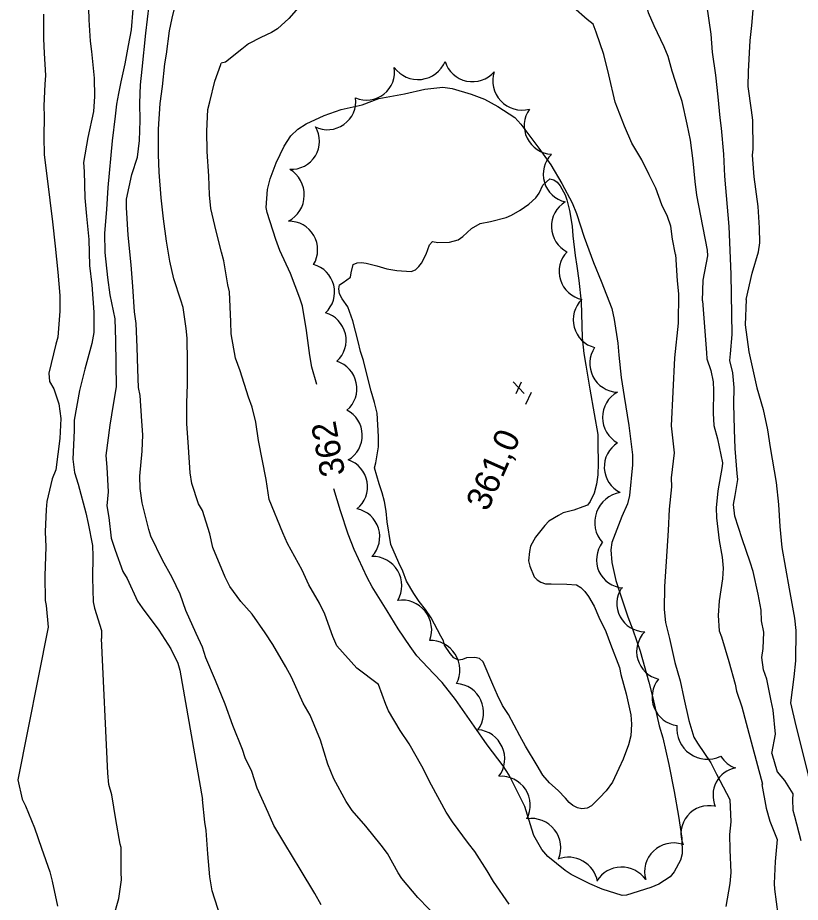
# Model space of a CAD drawing. Extents: x 287698 to 290158, y 5234163 to 5237182.
# Drawn here: x 288457.5 to 288552.3, y 5235917.4 to 5236024.6 of the extents above; entities that cross this region are included whole.
import ezdxf

# ---------------------------------------------------------------- set-up
doc = ezdxf.new("R2010")
doc.units = 0
for name, color, linetype in [('Niveau 1', 7, 'Continuous'), ('Niveau 2', 7, 'Continuous'), ('Niveau 3', 7, 'Continuous'), ('Niveau 4', 7, 'Continuous'), ('Niveau 44', 7, 'Continuous')]:
    doc.layers.add(name, color=color, linetype=linetype)

msp = doc.modelspace()

# ---------------------------------------------------------------- linework, layer by layer
at = {"layer": 'Niveau 1'}
for points in [[(288545.79, 5235990.47), (288546.52, 5235993.67), (288547.28, 5235996.23), (288547.44, 5235997.35), (288547.4, 5235999.16), (288547.23, 5236001.73), (288546.75, 5236005.33), (288546.55, 5236007.98), (288546.63, 5236008.7), (288546.57, 5236012.21), (288546.43, 5236013.41), (288546.01, 5236016.31), (288546.07, 5236018.11), (288546.25, 5236021.86), (288546.45, 5236023.69), (288546.8, 5236027.53)], [(288471.43, 5236025.67), (288471.22, 5236023.17), (288470.86, 5236021.27), (288470.44, 5236019.03), (288469.96, 5236016.86), (288469.66, 5236015.47), (288469.42, 5236014.16), (288469.25, 5236012.71), (288468.92, 5236009.7), (288468.37, 5236004.07), (288468.22, 5236001.39), (288467.96, 5235998.5), (288468, 5235996.15), (288468.32, 5235993.13), (288468.62, 5235991.04), (288469.21, 5235988.11), (288469.32, 5235985.49), (288469.37, 5235979.88), (288469.02, 5235977.75), (288468.64, 5235975.24), (288468.14, 5235971.54), (288468.25, 5235970.15), (288468.4, 5235967.14), (288468.25, 5235965.44), (288468.51, 5235964.03), (288468.79, 5235961.51), (288469.25, 5235960.07), (288470.21, 5235957.5), (288470.72, 5235956.62), (288471.98, 5235953.89), (288472.53, 5235953.06), (288474.57, 5235950.37), (288476.02, 5235948.12), (288476.88, 5235946.38), (288477.1, 5235945.5), (288479.85, 5235929.82)], [(288545.79, 5235990.47), (288545.64, 5235987.4), (288546.09, 5235984.12), (288547.05, 5235979.75), (288547.85, 5235977.13), (288548.35, 5235974.65), (288548.67, 5235972.5), (288549.42, 5235968.27), (288549.68, 5235965.62), (288549.87, 5235962.95), (288550.11, 5235960.4), (288550.53, 5235957.87), (288551, 5235955.39), (288551.64, 5235951.81), (288551.79, 5235950.32), (288551.76, 5235946.63), (288551.57, 5235944.7), (288551.17, 5235941.54), (288551.8, 5235938.75), (288553.24, 5235932.97), (288555.16, 5235921.59)], [(288482.41, 5235914.47), (288481.02, 5235918.77), (288480.73, 5235920.47), (288480.52, 5235923.25), (288480.3, 5235926.08), (288480.13, 5235927.09), (288479.85, 5235929.82)]]:
    msp.add_lwpolyline(points, dxfattribs=at)
at = {"layer": 'Niveau 2'}
for points in [[(288508.64, 5235915.2), (288505.96, 5235917.96), (288504.01, 5235920.24), (288503.6, 5235920.95), (288502.3, 5235923.26), (288501.53, 5235924.29), (288499.67, 5235926.61), (288498.01, 5235928.51), (288497.27, 5235929.59), (288495.77, 5235932.34), (288495.07, 5235934.1), (288494.15, 5235937.01), (288492.9, 5235940.06), (288492.06, 5235941.52), (288490.65, 5235944.66), (288489.96, 5235945.93), (288488.4, 5235948.62), (288487.47, 5235950.06), (288485.87, 5235952.32), (288484.51, 5235953.83), (288483.17, 5235955.66), (288482.61, 5235956.79), (288481.11, 5235960.41), (288480.75, 5235962.03), (288479.84, 5235964.87), (288479.37, 5235965.7), (288478.57, 5235968.14), (288478.35, 5235969.45), (288478.14, 5235972.54), (288477.97, 5235975.43), (288477.94, 5235977.94), (288478.04, 5235980.14), (288478.02, 5235982.9), (288478.01, 5235985.79), (288477.86, 5235986.97), (288477.53, 5235989.48), (288477.22, 5235990.37), (288476.39, 5235992.96), (288475.89, 5235995.11), (288475.5, 5235997.55), (288475.12, 5236000.26), (288474.84, 5236002.78), (288474.59, 5236005.92), (288474.51, 5236008.07), (288474.54, 5236011.14), (288474.74, 5236014.22), (288475.02, 5236016.29), (288475.27, 5236019.03), (288475.48, 5236020.24), (288475.87, 5236023.07), (288476.18, 5236024.59), (288476.91, 5236027.56)], [(288540.5, 5235990.31), (288540.56, 5235992.8), (288541.11, 5235995.75), (288541.09, 5235996.47), (288540.29, 5236000.62), (288539.78, 5236003.14), (288539.59, 5236004.77), (288539.36, 5236007.27), (288539.01, 5236009.81), (288538.63, 5236011.75), (288538, 5236014.48), (288537.56, 5236015.76), (288536.79, 5236018.16), (288536.33, 5236019.93), (288535.85, 5236021.1), (288534.61, 5236023.66), (288533.95, 5236025.25), (288533.62, 5236026.63), (288533.22, 5236028.42)], [(288466, 5236027.22), (288466.06, 5236024.38), (288466.23, 5236021.81), (288466.41, 5236020.54), (288466.72, 5236017.31), (288466.78, 5236015.08), (288466.64, 5236013.27), (288465.95, 5236010.1), (288465.42, 5236007.08), (288465.49, 5236005.99), (288465.6, 5236002.81), (288465.8, 5236000.58), (288466.06, 5235997.76), (288466.15, 5235994.61), (288466.43, 5235992.25), (288466.69, 5235988.95), (288466.69, 5235986.45), (288466.44, 5235985.14), (288465.58, 5235982), (288464.93, 5235979.42), (288464.3, 5235975.84), (288464.3, 5235974.59), (288464.15, 5235971.09), (288464.33, 5235969.49), (288464.77, 5235968.06), (288465.73, 5235964.61), (288466, 5235963.32), (288466.5, 5235960.62), (288466.56, 5235959.35), (288466.5, 5235956.72), (288466.59, 5235953.82), (288466.75, 5235953.02), (288467.61, 5235950.33), (288467.63, 5235949.36)], [(288492.12, 5236026.56), (288490.33, 5236024.55), (288488.97, 5236023.31), (288488.24, 5236022.85), (288486.94, 5236022.25), (288485.44, 5236021.49), (288484.62, 5236020.82), (288482.64, 5236019.26), (288482.14, 5236019.13), (288482.14, 5236019.13)], [(288494.23, 5235917.07), (288493.47, 5235918.43), (288491.7, 5235921.39), (288489.85, 5235924.46), (288488.51, 5235926.67), (288487.81, 5235928.24), (288486.49, 5235931.21), (288485.82, 5235933.22), (288485.02, 5235934.89), (288484.7, 5235935.91), (288483.55, 5235938.82), (288482.62, 5235941.38), (288481.42, 5235944.27), (288480.25, 5235947.03), (288479.84, 5235948.31), (288479.08, 5235949.97), (288477.82, 5235952.75), (288477.13, 5235954.74), (288476.16, 5235956.76), (288474.99, 5235958.84), (288473.6, 5235961.78), (288473.36, 5235962.59), (288472.56, 5235965.82), (288472.28, 5235967.54), (288472.24, 5235969.03), (288472.56, 5235972.08), (288472.62, 5235974.07), (288472.51, 5235975.71), (288472.28, 5235978.84), (288472.11, 5235979.81), (288472.02, 5235982.03), (288471.92, 5235984.7), (288471.8, 5235987.57), (288471.61, 5235988.99), (288471.41, 5235992.05), (288471.2, 5235994.67), (288470.86, 5235998.29), (288470.63, 5236001.63), (288470.66, 5236002.64), (288471.29, 5236005.61), (288471.98, 5236007.73), (288472.2, 5236009.76), (288472.28, 5236012.18), (288472.24, 5236014.28), (288472.33, 5236016.51), (288472.55, 5236018.42), (288473, 5236022.75), (288473.39, 5236026.17)], [(288527.6, 5236022.9), (288527.21, 5236023.86), (288526.51, 5236024.42), (288524.82, 5236025.88)], [(288544.07, 5235986.23), (288543.95, 5235993.53), (288543.73, 5235999.31), (288543.19, 5236005.42), (288543.05, 5236008.11), (288542.79, 5236011.25), (288542.61, 5236012.49), (288542.4, 5236015.04), (288542.09, 5236017.67), (288541.68, 5236020.47), (288541.53, 5236022.63), (288540.99, 5236026.25)], [(288460.58, 5236025.07), (288460.58, 5236022.1), (288460.67, 5236020.36), (288460.84, 5236017.63), (288460.73, 5236016.59), (288460.61, 5236013.95), (288460.67, 5236012.68), (288460.6, 5236010.18), (288460.65, 5236008.01), (288460.86, 5236006.42), (288461.34, 5236002.51), (288461.68, 5235999.87), (288462, 5235996.92), (288462.32, 5235993.78), (288462.57, 5235990.96), (288462.56, 5235989.04), (288462.31, 5235985.9), (288462.07, 5235985.04), (288461.21, 5235981.52), (288461.32, 5235980.51), (288461.85, 5235979.62), (288462.42, 5235977.82), (288462.66, 5235976.03), (288462.56, 5235973.62), (288462.06, 5235969.83), (288461.64, 5235968.7), (288461, 5235965.97), (288460.89, 5235964.99), (288460.8, 5235962.28), (288460.86, 5235960.46), (288460.76, 5235956.95), (288460.79, 5235953.95)], [(288537.2, 5235995.92), (288536.86, 5235997.79), (288536.63, 5235999.36), (288536.22, 5236000.53), (288535.53, 5236001.96), (288534.83, 5236003.97), (288534.02, 5236005.6), (288533.12, 5236007.41), (288531.9, 5236009.42), (288531.01, 5236011.5), (288529.9, 5236014.41), (288529.12, 5236017.73), (288528.5, 5236020.17), (288527.6, 5236022.9)], [(288501.19, 5235943.79), (288498.57, 5235945.77), (288496.15, 5235948.46), (288495.67, 5235949.58), (288494.7, 5235952.29), (288494.04, 5235953.64), (288492.74, 5235955.88), (288491.96, 5235957.64), (288490.18, 5235960.89), (288489.58, 5235962.16), (288487.93, 5235966.2), (288487.56, 5235968.63), (288486.66, 5235973.35), (288486.31, 5235975.61), (288485.87, 5235977.42), (288485.43, 5235978.63), (288484.43, 5235981.83), (288483.86, 5235983.34), (288483.32, 5235986.32), (288483.31, 5235987.76), (288483.12, 5235991.38), (288482.94, 5235992.26), (288482.45, 5235995.15), (288482.17, 5235996.2), (288481.52, 5235998.77), (288480.88, 5236001.49), (288480.7, 5236003.17), (288480.63, 5236005.41), (288480.44, 5236008.4), (288480.37, 5236010.9), (288480.52, 5236013.53), (288480.74, 5236014.46), (288481.36, 5236016.93), (288482.07, 5236018.95), (288482.14, 5236019.13)], [(288499.21, 5236014.08), (288501.23, 5236014.84), (288504.35, 5236015.41), (288506.81, 5236015.98), (288508.99, 5236016.22), (288510.14, 5236016.05), (288512.42, 5236015.37), (288514.03, 5236014.75), (288515.67, 5236013.89), (288517.73, 5236012.56), (288518.46, 5236011.74), (288520.63, 5236008.84), (288522.08, 5236006.79), (288523.41, 5236004.55), (288524.66, 5236002.2), (288525.22, 5236000.9), (288526.15, 5235998.04), (288527.27, 5235994.94), (288528.19, 5235992.69), (288529.47, 5235989.39), (288529.77, 5235988.06), (288530.2, 5235985.17), (288530.32, 5235983.73), (288530.61, 5235980.99), (288530.99, 5235978.71), (288531.54, 5235975.2), (288532, 5235971.63), (288531.99, 5235970.41), (288531.63, 5235966.7), (288531.38, 5235965.7), (288530.71, 5235964.16), (288529.49, 5235961), (288529.36, 5235960.09), (288529.5, 5235958.59), (288529.99, 5235956.39), (288530.48, 5235954.79), (288531.41, 5235952), (288532.03, 5235950.4), (288532.91, 5235947.81), (288533.97, 5235944.05), (288534.44, 5235942.16), (288535.23, 5235938.77), (288535.67, 5235937.29), (288536.4, 5235934.06), (288537.04, 5235930.81), (288537.59, 5235927.79), (288537.98, 5235925.12), (288538.02, 5235923.24), (288537.82, 5235922.48), (288537.06, 5235921.05), (288536.57, 5235920.44), (288535.19, 5235919.57), (288534.21, 5235919.14), (288531.26, 5235918.21), (288530.76, 5235918.2), (288528.32, 5235918.96), (288526.84, 5235919.59), (288524.54, 5235920.75), (288523.83, 5235921.23), (288521.72, 5235922.92), (288521, 5235923.75), (288520.05, 5235925.46), (288519.8, 5235926.23), (288518.93, 5235928.99), (288518.39, 5235930.12), (288517.05, 5235932.78), (288516.33, 5235933.93), (288514.39, 5235936.45), (288512.81, 5235938.71), (288510.54, 5235941.94), (288508.91, 5235944.01), (288507.86, 5235945.09), (288505.84, 5235947.26), (288505.02, 5235948.38), (288503.57, 5235950.51), (288502.25, 5235952.7), (288500.42, 5235955.62), (288499.82, 5235956.74), (288498.23, 5235960.14), (288497.5, 5235962.01), (288496.58, 5235964.83), (288495.79, 5235967.52)], [(288489.75, 5236009.08), (288490.55, 5236010.31), (288491.4, 5236011.13), (288492.42, 5236011.77), (288494.6, 5236012.77), (288496.66, 5236013.5), (288499.21, 5236014.08)], [(288493.71, 5235980.15), (288493.11, 5235982.26), (288492.88, 5235983.69), (288492.45, 5235986.72), (288491.99, 5235989.66), (288491.65, 5235990.64), (288490.52, 5235993.62), (288489.23, 5235996.42), (288488.73, 5235997.76), (288487.68, 5236001.03), (288487.58, 5236001.63), (288487.74, 5236003.82), (288488.08, 5236005.11), (288488.8, 5236007.05), (288489.75, 5236009.08)], [(288537.2, 5235995.92), (288537.42, 5235992.72), (288537.58, 5235991.15), (288537.51, 5235987.61), (288537.08, 5235983.4), (288536.7, 5235975.14)], [(288540.5, 5235990.31), (288540.98, 5235984.02), (288541, 5235983.29), (288541.49, 5235981.84), (288541.78, 5235980.47), (288541.81, 5235979.43), (288541.79, 5235976.7), (288541.87, 5235975.17), (288542.3, 5235973.57), (288542.9, 5235970.66), (288542.88, 5235970.21), (288542.35, 5235967.27), (288542.14, 5235965.21), (288542.16, 5235963.98), (288542.51, 5235961.22), (288542.88, 5235959.2), (288542.99, 5235957.87), (288542.89, 5235956.59), (288542.51, 5235953.92), (288542.37, 5235952.13), (288542.51, 5235950.29), (288542.78, 5235949.54), (288543.66, 5235946.58), (288544.45, 5235943.82), (288544.59, 5235942.96), (288545.25, 5235941.06), (288545.77, 5235939.08)], [(288548.89, 5235935.4), (288549.33, 5235937.75), (288549.06, 5235940.65), (288548.82, 5235941.81), (288548.28, 5235944.42), (288547.86, 5235945.57), (288547.66, 5235947.07), (288547.82, 5235948.13), (288547.93, 5235950.13), (288547.63, 5235951.48), (288547.61, 5235952.78), (288547.25, 5235954.75), (288546.63, 5235957.5), (288546.26, 5235958.62), (288545.28, 5235961.43), (288544.41, 5235964.19), (288544.22, 5235965.59), (288544.44, 5235966.69), (288544.76, 5235968.62), (288544.7, 5235969.38), (288544.46, 5235972.39), (288544.37, 5235974.71), (288544.27, 5235977.8), (288544.3, 5235979.8), (288544.14, 5235981.58), (288543.81, 5235983.08), (288543.87, 5235983.88), (288544.07, 5235986.23)], [(288536.7, 5235975.14), (288537.03, 5235971.87), (288536.69, 5235968.85), (288536.71, 5235967.75), (288536.45, 5235965.02), (288536.31, 5235962.45), (288536.08, 5235958.68), (288535.88, 5235955.66), (288535.85, 5235952.87), (288536.01, 5235951.28), (288536.49, 5235949.35), (288537.13, 5235946.43), (288537.76, 5235944.23), (288538.22, 5235942.12), (288538.84, 5235939.4), (288539.42, 5235937.4), (288539.86, 5235936.67), (288541.49, 5235934.28), (288542.18, 5235932.89)], [(288460.79, 5235953.95), (288460.89, 5235953.34), (288461.13, 5235950.71)], [(288461.13, 5235950.71), (288457.45, 5235932.23), (288457.99, 5235929.86), (288458.41, 5235929.08), (288459.49, 5235926.4), (288460.34, 5235923.94), (288461.36, 5235921.06), (288461.61, 5235919.93), (288462.29, 5235916.89)], [(288469.03, 5235915.38), (288469.71, 5235917.81), (288470.02, 5235920.07), (288470, 5235921.01), (288470, 5235923.99), (288469.86, 5235924.43), (288469.36, 5235927.39), (288468.86, 5235930.38), (288468.52, 5235931.65), (288468.37, 5235933.01), (288467.63, 5235949.36)], [(288517.04, 5235917.13), (288515.14, 5235919.88), (288514.39, 5235921.17), (288512.89, 5235923.51), (288512.11, 5235924.5), (288510.16, 5235927.14), (288509.39, 5235928.31), (288507.64, 5235931.58), (288506.47, 5235933.88), (288504.93, 5235936.57), (288503.82, 5235938.18), (288502.42, 5235940.57), (288502.1, 5235941.34), (288501.19, 5235943.79)], [(288545.77, 5235939.08), (288547.74, 5235931.7), (288547.66, 5235931.66), (288548.19, 5235928.78), (288548.66, 5235927.21), (288549.54, 5235924.97), (288549.3, 5235922.31), (288549.15, 5235919.63), (288549.23, 5235918.97), (288549.61, 5235915.9), (288549.97, 5235912.96), (288550.01, 5235911.86), (288549.9, 5235908.44), (288549.72, 5235907.32), (288549.26, 5235904.52), (288549.01, 5235903.61), (288548.2, 5235900.76), (288547.56, 5235898.93), (288546.42, 5235896.01), (288545.31, 5235893.46), (288544.42, 5235891.81), (288543.59, 5235890.61), (288541.89, 5235888.53), (288541.5, 5235888.17)], [(288548.89, 5235935.4), (288549.53, 5235933.18), (288550.42, 5235932.12), (288551.44, 5235930.52), (288551.41, 5235929.84), (288551.43, 5235928.54), (288551.65, 5235927.82), (288552.4, 5235924.85)], [(288542.18, 5235932.89), (288543.78, 5235929.84), (288543.92, 5235927.14), (288543.77, 5235925.59), (288543.78, 5235923.73), (288543.9, 5235920.97), (288543.78, 5235919.66), (288543.32, 5235916.86)]]:
    msp.add_lwpolyline(points, dxfattribs=at)
at = {"layer": 'Niveau 3'}
for p, q in [((288517.54, 5235980.47), (288518.85, 5235979.07)), ((288517.9, 5235979.05), (288518.54, 5235980.48)), ((288519.08, 5235977.76), (288519.73, 5235979.23))]:
    msp.add_line(p, q, dxfattribs=at)
at = {"layer": 'Niveau 4'}
for points in [[(288502.7, 5235960.76), (288502.24, 5235963.5), (288502.13, 5235964.79), (288501.93, 5235965.95), (288501.65, 5235967.04), (288501.26, 5235968.12), (288500.72, 5235970.06), (288500.86, 5235970.64), (288501.2, 5235972.6), (288501.18, 5235973.87), (288501.04, 5235976.68), (288500.73, 5235977.96), (288500.32, 5235979.36), (288499.81, 5235981.25), (288499.39, 5235983.07), (288499.02, 5235984.18), (288498.75, 5235985.36), (288498.09, 5235987.88), (288497.48, 5235989.59), (288496.78, 5235990.56), (288496.48, 5235991.16), (288496.38, 5235991.76), (288496.48, 5235992.25), (288496.9, 5235992.54), (288497.8, 5235993.19), (288497.88, 5235993.72), (288498.14, 5235994.71), (288498.62, 5235994.92), (288499.14, 5235994.96), (288499.71, 5235994.86), (288501.01, 5235994.56), (288502.21, 5235994.2), (288503.43, 5235993.98), (288505.14, 5235993.87), (288505.67, 5235994.08), (288506.09, 5235994.46), (288506.39, 5235994.89), (288506.96, 5235995.98), (288507.4, 5235997.1), (288507.74, 5235997.51), (288508.41, 5235997.39), (288509.79, 5235997.41), (288510.85, 5235997.71), (288511.41, 5235998.11), (288512.48, 5235999.07), (288513.51, 5235999.67), (288514.79, 5235999.93), (288516.66, 5236000.4), (288517.32, 5236000.7), (288518.38, 5236001.29), (288519.41, 5236002.01), (288520.29, 5236002.81), (288520.66, 5236003.35), (288521.12, 5236004.33), (288521.96, 5236005.12), (288522.45, 5236005), (288522.87, 5236004.68), (288523.21, 5236004.24), (288523.84, 5236003.18), (288524.05, 5236002.57), (288524.35, 5236001.25), (288524.68, 5235999.36), (288524.77, 5235998.2), (288525.04, 5235995.82), (288525.25, 5235994.51), (288525.47, 5235992.77), (288525.76, 5235990.17), (288525.8, 5235988.79), (288525.89, 5235985.8), (288526.09, 5235983.9), (288526.32, 5235982.52), (288526.83, 5235979.6), (288527.35, 5235976.59), (288527.78, 5235974.09), (288527.77, 5235972.96), (288527.83, 5235970.58), (288527.78, 5235969.22), (288527.64, 5235968.06), (288527.35, 5235966.97), (288526.88, 5235965.95), (288526.53, 5235965.51), (288525.98, 5235965.33), (288524.88, 5235964.91), (288523.59, 5235964.58), (288523.01, 5235964.27), (288521.85, 5235963.6), (288521.37, 5235963.04), (288520.25, 5235961.66), (288519.63, 5235960.55), (288519.5, 5235959.91), (288519.39, 5235958.79), (288519.56, 5235958.12), (288520.09, 5235956.85), (288520.44, 5235956.46), (288520.88, 5235956.17), (288521.43, 5235955.99), (288522.13, 5235955.97), (288524.04, 5235955.96), (288525.19, 5235955.86), (288525.72, 5235955.52), (288526.2, 5235955.05)], [(288526.2, 5235955.05), (288526.66, 5235954.44), (288527.34, 5235953.29), (288527.92, 5235951.96), (288528.74, 5235950.21), (288529.31, 5235948.68), (288530.4, 5235945.82), (288530.59, 5235945), (288531.21, 5235942.66), (288531.81, 5235940.09), (288531.89, 5235938.97), (288531.79, 5235937.55), (288531.51, 5235936.47), (288530.86, 5235934.73), (288530.35, 5235933.58), (288529.57, 5235931.93), (288528.81, 5235930.89), (288527.99, 5235930.02), (288527.01, 5235929.08), (288526.48, 5235928.77), (288525.83, 5235928.7), (288525.31, 5235928.81), (288524.75, 5235929.12), (288524.33, 5235929.46), (288523.88, 5235929.98), (288522.98, 5235930.91), (288521.93, 5235931.85), (288521.13, 5235932.78), (288520.43, 5235933.97), (288519.01, 5235936.29), (288518.33, 5235937.55), (288516.96, 5235940.14), (288516.25, 5235941.22), (288515.61, 5235942.47), (288515.06, 5235943.78), (288513.9, 5235946.53), (288513.45, 5235946.91), (288512.88, 5235947.05), (288511.86, 5235947.02), (288511.39, 5235946.81), (288510.88, 5235946.71), (288510.34, 5235947), (288509.87, 5235947.52), (288509.19, 5235948.56), (288509.06, 5235949.06), (288508.76, 5235949.63), (288507.57, 5235951.85), (288506.88, 5235952.86), (288506.11, 5235953.84), (288505.47, 5235954.83), (288504.59, 5235956.29), (288504.15, 5235957.54), (288503.65, 5235958.52), (288502.7, 5235960.76)]]:
    msp.add_lwpolyline(points, dxfattribs=at)
at = {"layer": 'Niveau 44'}
for centre, radius, start, end in [((288495.01, 5236014.49), 3.43, 243.9667, 7.2048), ((288522.35, 5236011.56), 3.49, 145.1525, 266.9695), ((288524.6, 5236005.65), 3.43, 135.0643, 257.0362), ((288525.61, 5235999.34), 3.45, 121.0603, 243.1117), ((288526.57, 5235993.87), 3.47, 136.4541, 258.0849), ((288528.25, 5235987.99), 3.45, 133.9559, 255.8213), ((288530.28, 5235982.71), 3.47, 146.1194, 268.0248), ((288495.12, 5235979.67), 3.46, 310.711, 72.7637), ((288531.88, 5235976.17), 3.52, 119.2584, 241.2997), ((288495.78, 5235973.99), 3.45, 300.4847, 62.5501), ((288532.02, 5235970.16), 3.45, 122.1344, 243.9512), ((288496.41, 5235967.75), 3.45, 309.114, 71.122), ((288531.1, 5235963.42), 3.68, 99.1626, 221.3266), ((288497.89, 5235961.69), 3.46, 316.3525, 78.299), ((288500.48, 5235955.77), 3.54, 329.4957, 91.5105), ((288510.41, 5235940.38), 3.53, 323.6882, 85.875), ((288512.95, 5235934.76), 3.55, 323.343, 85.0703)]:
    msp.add_arc(centre, radius, start, end, dxfattribs=at)
for centre, major_axis, ratio, start_param, end_param in [((288505.99, 5236020.69), (0.42, -3.52), 0.999917, 5.217381, 7.345615), ((288512.59, 5236020.37), (-0.72, -3.41), 0.999995, 5.219571, 7.348896), ((288499.71, 5236018.11), (2.18, -2.69), 0.992003, 5.214844, 7.32301), ((288518.61, 5236017), (3.42, -1), 0.999995, 3.114899, 5.244286), ((288490.62, 5236009.67), (1.78, 2.92), 0.999939, 3.632922, 5.791856), ((288488.6, 5236003.15), (3.6, -0.08), 0.998862, 5.21955, 7.342418), ((288490.34, 5235996.49), (3.24, 1.27), 0.999833, 5.371404, 7.497724), ((288492.41, 5235991.38), (3.36, 0.82), 0.999072, 5.220431, 7.346975), ((288493.82, 5235985.53), (3.36, 0.8), 0.999995, 5.216818, 7.345195), ((288531.05, 5235958.91), (1.41, -3.12), 0.999862, 3.634851, 5.789927), ((288533.51, 5235953.59), (-3.27, -1.02), 0.99471, 5.388534, 7.54315), ((288504.24, 5235950.57), (-2.19, 2.74), 0.951396, 3.633244, 5.791534), ((288535.98, 5235947.79), (-3.36, -0.93), 0.987348, 5.243594, 7.346718), ((288507.67, 5235945.67), (-1.87, 2.97), 0.951122, 3.63557, 5.789208), ((288537.84, 5235942.25), (-3.22, -1.29), 0.999913, 5.219714, 7.344201), ((288541.08, 5235938.43), (3.36, 1.58), 0.999986, 2.596499, 4.72207), ((288545.18, 5235937.29), (-0.07, -3.72), 0.822164, 5.358937, 6.073122), ((288545.23, 5235930.27), (-2.72, 2.21), 0.980304, 5.606892, 7.351491), ((288516.07, 5235929.12), (2.94, 1.95), 0.999995, 5.218222, 7.346439), ((288541.35, 5235925.62), (-2.72, 2.21), 0.980304, 5.192544, 7.351491), ((288519.75, 5235923.99), (-3.29, 1.3), 0.999995, 3.11768, 5.24401), ((288536.98, 5235921.06), (-3.23, 1.39), 0.994831, 4.812524, 6.96464), ((288524.39, 5235919.42), (-2.68, 2.28), 0.946493, 4.023778, 5.802527), ((288530.71, 5235918.21), (-3.46, 0.63), 0.968627, 3.922135, 5.925084)]:
    msp.add_ellipse(centre, major_axis=major_axis, ratio=ratio, start_param=start_param, end_param=end_param, dxfattribs=at)

# ---------------------------------------------------------------- texts
at = {"layer": 'Niveau 2'}
msp.add_text('362', height=3, rotation=100.6065, dxfattribs=at).set_placement((288497.18, 5235969.3))
at = {"layer": 'Niveau 3'}
msp.add_text('361,0', height=3, rotation=66.1217, dxfattribs=at).set_placement((288514.42, 5235964.65))

doc.saveas('drawing.dxf')
